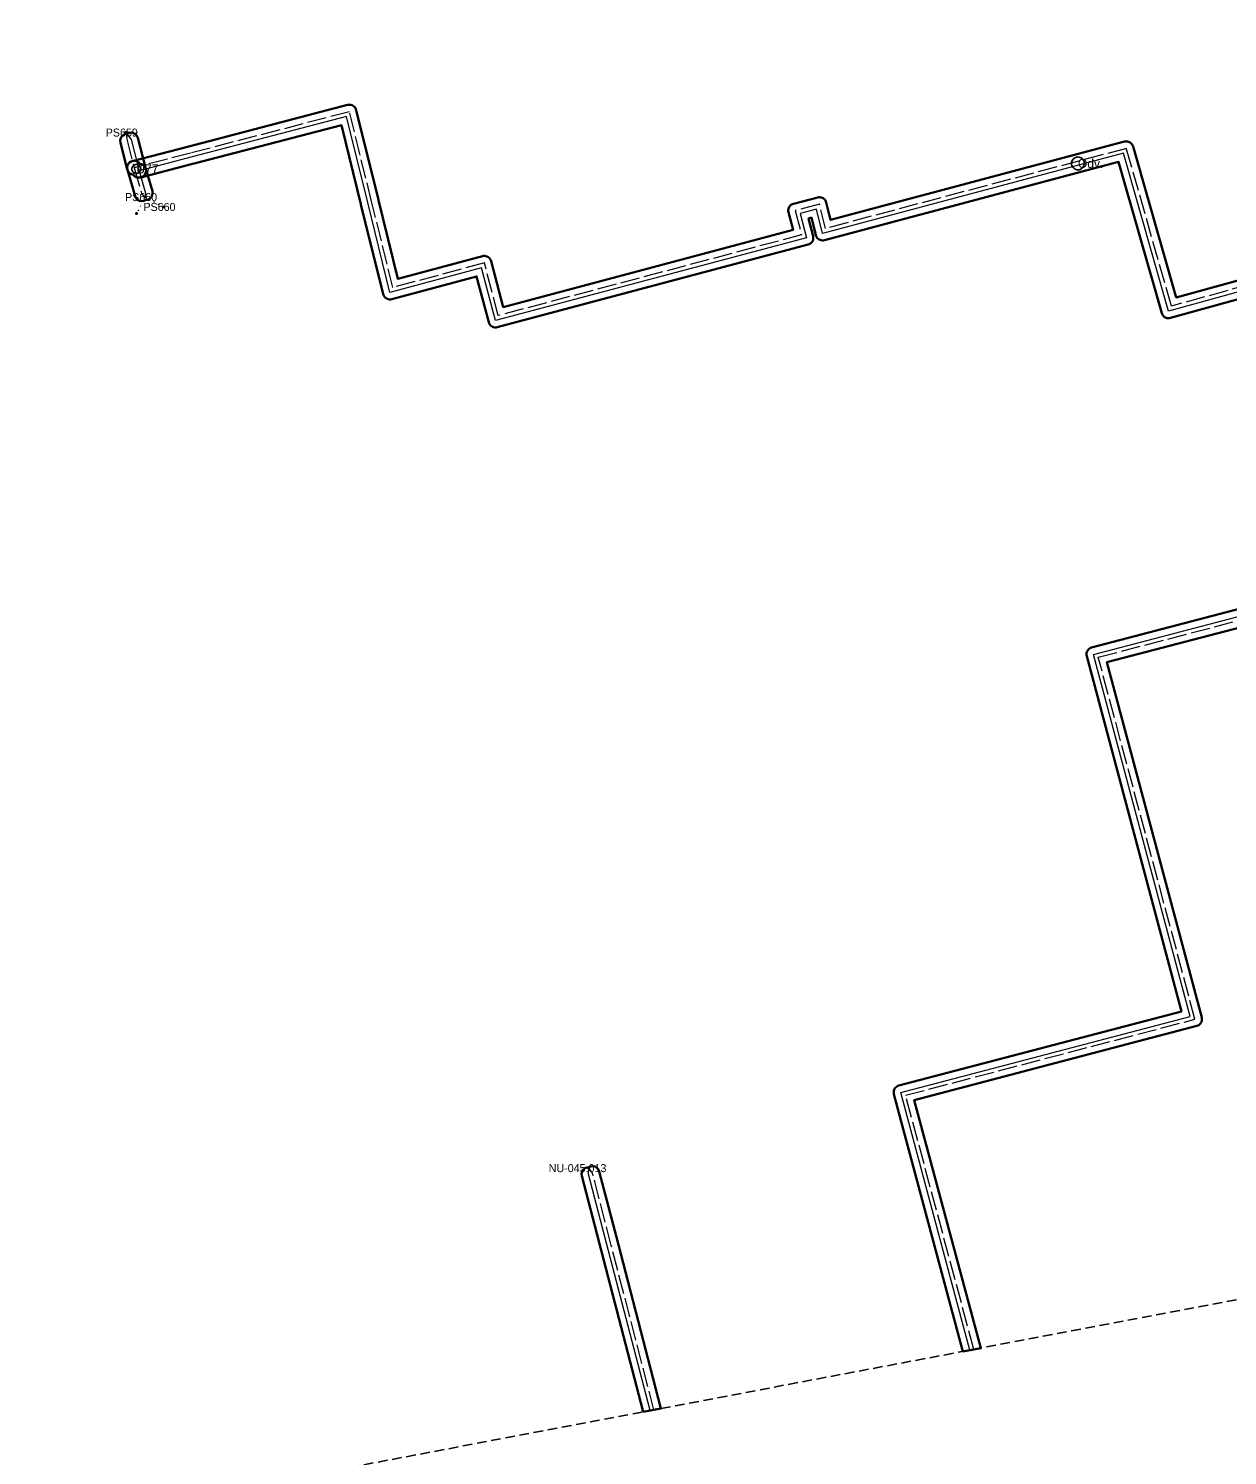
# Model space of a CAD drawing. Extents: x -452602 to -451136, y -1100088 to -1099653.
# Drawn here: x -451646 to -451526.1, y -1099905.8 to -1099763.2 of the extents above; entities that cross this region are included whole.
import ezdxf

# ---------------------------------------------------------------- set-up
doc = ezdxf.new("R2010")
doc.units = 0
doc.header["$LTSCALE"] = 0.32
doc.header["$PDMODE"] = 32
doc.header["$PDSIZE"] = 0.16
for name, pattern in [('DOTTED', [1.5, 0.3, -1.2]), ('LONG_DASHED', [7.5, 6, -1.5]), ('MEDIUM_DASHED', [4.5, 3, -1.5])]:
    doc.linetypes.add(name, pattern=pattern)
for name, color, linetype, lineweight in [('2', 7, 'Continuous', 13), ('3', 7, 'Continuous', 25), ('62', 7, 'MEDIUM_DASHED', 25), ('8', 7, 'Continuous', 35)]:
    doc.layers.add(name, color=color, linetype=linetype, lineweight=lineweight)
doc.layers.add('4', color=7, linetype='Continuous')
doc.layers.add('7', color=7, linetype='Continuous')

msp = doc.modelspace()

# ---------------------------------------------------------------- linework, layer by layer
at = {"layer": '2', "linetype": 'LONG_DASHED'}
for p, q in [((-451629.758, -1099775.646), (-451635.409, -1099777.116)), ((-451589.561, -1099877.625), (-451589.942, -1099877.122)), ((-451587.686, -1099884.846), (-451589.561, -1099877.625)), ((-451583.416, -1099901.289), (-451587.686, -1099884.846))]:
    msp.add_line(p, q, dxfattribs=at)
at = {"layer": '2'}
for p, q in [((-451629.595, -1099776.017), (-451634.909, -1099777.401)), ((-451589.95, -1099877.725), (-451589.942, -1099877.122)), ((-451583.81, -1099901.363), (-451589.95, -1099877.725))]:
    msp.add_line(p, q, dxfattribs=at)
at = {"layer": '2', "linetype": 'DOTTED'}
for q in [(-451635.162, -1099781.684), (-451632.472, -1099781.025)]:
    msp.add_line((-451634.313, -1099780.041), q, dxfattribs=at)
at = {"layer": '2', "linetype": 'LONG_DASHED'}
for points in [[(-451440.258, -1099765.721), (-451453.851, -1099769.417), (-451480.917, -1099777.002), (-451500.994, -1099782.511), (-451500.212, -1099785.292), (-451504.472, -1099786.44), (-451505.212, -1099783.669), (-451531.662, -1099790.934), (-451536.175, -1099775.177), (-451566.255, -1099783.181), (-451566.862, -1099780.756), (-451569.284, -1099781.379), (-451568.655, -1099783.82), (-451598.982, -1099791.89), (-451600.376, -1099786.618), (-451609.527, -1099789.083), (-451611.651, -1099780.495)], [(-451611.651, -1099780.495), (-451613.87, -1099771.51), (-451629.758, -1099775.646)], [(-451636.245, -1099773.591), (-451636.097, -1099774.397), (-451635.409, -1099777.116)], [(-451635.409, -1099777.116), (-451634.637, -1099779.752), (-451634.313, -1099780.041)], [(-451551.433, -1099895.241), (-451558.248, -1099869.833), (-451529.317, -1099862.234), (-451538.976, -1099826.048), (-451523.454, -1099821.982), (-451522.711, -1099824.236), (-451512.799, -1099821.592), (-451513.524, -1099818.868), (-451509.196, -1099817.785), (-451508.559, -1099820.425), (-451468.961, -1099809.725), (-451467.595, -1099809.356), (-451466.163, -1099814.028)]]:
    msp.add_lwpolyline(points, dxfattribs=at)
at = {"layer": '2'}
for points in [[(-451440.543, -1099766.212), (-451500.5, -1099782.791), (-451499.718, -1099785.574), (-451504.756, -1099786.93), (-451505.494, -1099784.161), (-451531.96, -1099791.453), (-451536.46, -1099775.666), (-451566.551, -1099783.675), (-451567.153, -1099781.244), (-451568.797, -1099781.667), (-451568.176, -1099784.107), (-451599.266, -1099792.381), (-451600.66, -1099787.109), (-451609.817, -1099789.576), (-451612.038, -1099780.59)], [(-451612.038, -1099780.59), (-451614.163, -1099772), (-451629.595, -1099776.017)], [(-451636.245, -1099773.591), (-451635.708, -1099774.296), (-451634.909, -1099777.401)], [(-451634.909, -1099777.401), (-451634.252, -1099779.64), (-451634.313, -1099780.041)], [(-451551.827, -1099895.315), (-451558.739, -1099869.548), (-451529.806, -1099861.951), (-451539.465, -1099825.761), (-451523.193, -1099821.5), (-451522.45, -1099823.752), (-451513.289, -1099821.307), (-451514.016, -1099818.579), (-451508.902, -1099817.3), (-451508.266, -1099819.931), (-451469.019, -1099809.326), (-451467.315, -1099808.865), (-451465.807, -1099813.902)]]:
    msp.add_lwpolyline(points, dxfattribs=at)
at = {"layer": '3'}
for points in [[(-451635.176, -1099776.777), (-451635.098, -1099776.784), (-451635.023, -1099776.804), (-451634.952, -1099776.837), (-451634.888, -1099776.881), (-451634.833, -1099776.937), (-451634.788, -1099777.001), (-451634.755, -1099777.071), (-451634.735, -1099777.147), (-451634.728, -1099777.225), (-451634.735, -1099777.302), (-451634.755, -1099777.378), (-451634.788, -1099777.448), (-451634.833, -1099777.512), (-451634.888, -1099777.567), (-451634.952, -1099777.612), (-451635.023, -1099777.645), (-451635.098, -1099777.665), (-451635.176, -1099777.672), (-451635.253, -1099777.665), (-451635.329, -1099777.645), (-451635.399, -1099777.612), (-451635.463, -1099777.567), (-451635.519, -1099777.512), (-451635.563, -1099777.448), (-451635.596, -1099777.378), (-451635.616, -1099777.302), (-451635.623, -1099777.225), (-451635.616, -1099777.147), (-451635.596, -1099777.071), (-451635.563, -1099777.001), (-451635.519, -1099776.937), (-451635.463, -1099776.881), (-451635.399, -1099776.837), (-451635.329, -1099776.804), (-451635.253, -1099776.784)], [(-451541.016, -1099776.031), (-451540.904, -1099776.041), (-451540.796, -1099776.07), (-451540.695, -1099776.117), (-451540.603, -1099776.181), (-451540.524, -1099776.26), (-451540.46, -1099776.352), (-451540.412, -1099776.454), (-451540.383, -1099776.562), (-451540.373, -1099776.673), (-451540.383, -1099776.785), (-451540.412, -1099776.893), (-451540.46, -1099776.994), (-451540.524, -1099777.086), (-451540.603, -1099777.165), (-451540.695, -1099777.229), (-451540.796, -1099777.277), (-451540.904, -1099777.306), (-451541.016, -1099777.315), (-451541.127, -1099777.306), (-451541.235, -1099777.277), (-451541.337, -1099777.229), (-451541.428, -1099777.165), (-451541.508, -1099777.086), (-451541.572, -1099776.994), (-451541.619, -1099776.893), (-451541.648, -1099776.785), (-451541.658, -1099776.673), (-451541.648, -1099776.562), (-451541.619, -1099776.454), (-451541.572, -1099776.352), (-451541.508, -1099776.26), (-451541.428, -1099776.181), (-451541.337, -1099776.117), (-451541.235, -1099776.07), (-451541.127, -1099776.041)]]:
    msp.add_lwpolyline(points, close=True, dxfattribs=at)
at = {"layer": '4'}
for p in [(-451636.245, -1099773.591), (-451634.313, -1099780.041), (-451632.472, -1099781.025), (-451635.162, -1099781.684), (-451589.942, -1099877.122)]:
    msp.add_point(p, dxfattribs=at)
at = {"layer": '62'}
msp.add_lwpolyline([(-451137.485, -1099816.961), (-452572.169, -1100088.267), (-452602.314, -1099919.678), (-451137.485, -1099652.838), (-451136.368, -1099701.963)], close=True, dxfattribs=at)
at = {"layer": '7'}
for p in [(-451636.245, -1099773.591), (-451634.313, -1099780.041), (-451589.942, -1099877.122)]:
    msp.add_point(p, dxfattribs=at)
at = {"layer": '8'}
for points in [[(-451635.962, -1099776.688), (-451635.884, -1099776.603), (-451635.794, -1099776.532), (-451635.693, -1099776.477), (-451635.585, -1099776.439), (-451629.935, -1099774.968), (-451614.047, -1099770.832), (-451613.938, -1099770.813), (-451613.827, -1099770.811), (-451613.718, -1099770.826), (-451613.612, -1099770.859), (-451613.512, -1099770.908), (-451613.422, -1099770.972), (-451613.343, -1099771.049), (-451613.277, -1099771.138), (-451613.226, -1099771.236), (-451613.191, -1099771.342), (-451610.971, -1099780.326), (-451610.969, -1099780.336), (-451609.019, -1099788.222), (-451600.559, -1099785.943), (-451600.45, -1099785.922), (-451600.34, -1099785.919), (-451600.231, -1099785.934), (-451600.125, -1099785.965), (-451600.026, -1099786.013), (-451599.935, -1099786.075), (-451599.855, -1099786.151), (-451599.789, -1099786.239), (-451599.736, -1099786.335), (-451599.7, -1099786.439), (-451598.484, -1099791.034), (-451569.506, -1099783.322), (-451569.962, -1099781.553), (-451569.98, -1099781.445), (-451569.982, -1099781.335), (-451569.967, -1099781.227), (-451569.935, -1099781.122), (-451569.886, -1099781.023), (-451569.823, -1099780.933), (-451569.747, -1099780.854), (-451569.659, -1099780.788), (-451569.562, -1099780.737), (-451569.458, -1099780.701), (-451567.037, -1099780.078), (-451566.928, -1099780.059), (-451566.818, -1099780.058), (-451566.709, -1099780.073), (-451566.604, -1099780.106), (-451566.505, -1099780.155), (-451566.414, -1099780.218), (-451566.336, -1099780.295), (-451566.27, -1099780.384), (-451566.219, -1099780.482), (-451566.184, -1099780.586), (-451565.748, -1099782.322), (-451536.355, -1099774.5), (-451536.237, -1099774.479), (-451536.116, -1099774.479), (-451535.997, -1099774.5), (-451535.884, -1099774.54), (-451535.779, -1099774.6), (-451535.686, -1099774.676), (-451535.607, -1099774.768), (-451535.546, -1099774.871), (-451535.503, -1099774.984), (-451531.179, -1099790.075), (-451505.397, -1099782.994)], [(-451505.988, -1099785.024), (-451531.774, -1099792.128), (-451531.894, -1099792.15), (-451532.015, -1099792.151), (-451532.135, -1099792.131), (-451532.249, -1099792.091), (-451532.355, -1099792.032), (-451532.449, -1099791.955), (-451532.528, -1099791.863), (-451532.59, -1099791.759), (-451532.633, -1099791.645), (-451536.944, -1099776.52), (-451566.371, -1099784.351), (-451566.48, -1099784.371), (-451566.591, -1099784.373), (-451566.701, -1099784.358), (-451566.808, -1099784.326), (-451566.907, -1099784.277), (-451566.998, -1099784.213), (-451567.078, -1099784.136), (-451567.144, -1099784.046), (-451567.196, -1099783.948), (-451567.231, -1099783.843), (-451567.663, -1099782.098), (-451567.946, -1099782.171), (-451567.497, -1099783.934), (-451567.478, -1099784.054), (-451567.479, -1099784.175), (-451567.501, -1099784.294), (-451567.543, -1099784.408), (-451567.605, -1099784.512), (-451567.683, -1099784.605), (-451567.777, -1099784.682), (-451567.882, -1099784.742), (-451567.996, -1099784.783), (-451599.086, -1099793.057), (-451599.206, -1099793.078), (-451599.327, -1099793.078), (-451599.447, -1099793.057), (-451599.562, -1099793.015), (-451599.667, -1099792.954), (-451599.76, -1099792.875), (-451599.839, -1099792.782), (-451599.9, -1099792.677), (-451599.942, -1099792.562), (-451601.157, -1099787.967), (-451609.634, -1099790.251), (-451609.744, -1099790.272), (-451609.855, -1099790.274), (-451609.965, -1099790.26), (-451610.072, -1099790.227), (-451610.172, -1099790.179), (-451610.263, -1099790.115), (-451610.343, -1099790.037), (-451610.409, -1099789.948), (-451610.461, -1099789.849), (-451610.496, -1099789.743), (-451612.714, -1099780.773), (-451612.718, -1099780.758), (-451612.722, -1099780.744), (-451614.672, -1099772.855), (-451629.412, -1099776.693), (-451629.419, -1099776.695), (-451629.426, -1099776.696), (-451634.732, -1099778.078), (-451634.779, -1099778.088), (-451634.853, -1099778.098), (-451634.972, -1099778.098), (-451635.089, -1099778.077), (-451635.2, -1099778.037), (-451635.304, -1099777.978), (-451635.396, -1099777.903), (-451635.474, -1099777.813), (-451635.587, -1099777.793), (-451635.695, -1099777.755), (-451635.796, -1099777.7), (-451635.886, -1099777.628), (-451635.964, -1099777.543), (-451636.026, -1099777.447), (-451636.071, -1099777.342), (-451636.099, -1099777.23), (-451636.109, -1099777.115), (-451636.099, -1099777.001), (-451636.071, -1099776.89), (-451636.025, -1099776.784)], [(-451523.913, -1099822.825), (-451538.118, -1099826.546), (-451528.64, -1099862.054), (-451528.62, -1099862.162), (-451528.618, -1099862.272), (-451528.632, -1099862.381), (-451528.664, -1099862.487), (-451528.711, -1099862.586), (-451528.774, -1099862.677), (-451528.85, -1099862.756), (-451528.938, -1099862.823), (-451529.035, -1099862.875), (-451529.139, -1099862.912), (-451557.39, -1099870.331), (-451550.743, -1099895.11), (-451552.517, -1099895.446), (-451559.415, -1099869.73), (-451559.435, -1099869.621), (-451559.438, -1099869.511), (-451559.423, -1099869.402), (-451559.391, -1099869.296), (-451559.344, -1099869.197), (-451559.281, -1099869.106), (-451559.205, -1099869.027), (-451559.117, -1099868.96), (-451559.02, -1099868.908), (-451558.916, -1099868.872), (-451530.664, -1099861.452), (-451540.142, -1099825.942), (-451540.162, -1099825.834), (-451540.164, -1099825.723), (-451540.15, -1099825.614), (-451540.118, -1099825.509), (-451540.071, -1099825.41), (-451540.008, -1099825.319), (-451539.932, -1099825.239), (-451539.844, -1099825.173), (-451539.747, -1099825.12), (-451539.643, -1099825.084), (-451523.37, -1099820.822)]]:
    msp.add_lwpolyline(points, dxfattribs=at)
for points in [[(-451635.467, -1099777.812), (-451635.668, -1099777.766), (-451635.857, -1099777.654), (-451636.001, -1099777.489), (-451636.087, -1099777.288), (-451636.775, -1099774.568), (-451636.795, -1099774.35), (-451636.746, -1099774.136), (-451636.634, -1099773.948), (-451636.469, -1099773.804), (-451636.268, -1099773.718), (-451636.071, -1099773.7), (-451635.883, -1099773.619), (-451635.665, -1099773.598), (-451635.451, -1099773.645), (-451635.263, -1099773.757), (-451635.118, -1099773.921), (-451635.031, -1099774.122), (-451634.231, -1099777.226), (-451634.21, -1099777.444), (-451634.257, -1099777.658), (-451634.369, -1099777.846), (-451634.533, -1099777.991), (-451634.734, -1099778.078), (-451634.952, -1099778.099), (-451635.166, -1099778.052), (-451635.354, -1099777.94)], [(-451634.842, -1099776.71), (-451634.673, -1099776.741), (-451634.481, -1099776.846), (-451634.33, -1099777.006), (-451634.237, -1099777.204), (-451633.581, -1099779.444), (-451633.553, -1099779.661), (-451633.593, -1099779.876), (-451633.699, -1099780.068), (-451633.858, -1099780.219), (-451634.056, -1099780.312), (-451634.258, -1099780.338), (-451634.44, -1099780.424), (-451634.657, -1099780.452), (-451634.872, -1099780.412), (-451635.064, -1099780.307), (-451635.215, -1099780.147), (-451635.308, -1099779.949), (-451636.08, -1099777.313), (-451636.108, -1099777.096), (-451636.068, -1099776.881), (-451635.962, -1099776.689), (-451635.803, -1099776.538), (-451635.605, -1099776.445), (-451635.388, -1099776.417), (-451635.173, -1099776.457), (-451634.981, -1099776.563)], [(-451584.499, -1099901.494), (-451590.627, -1099877.901), (-451590.648, -1099877.684), (-451590.601, -1099877.47), (-451590.49, -1099877.281), (-451590.326, -1099877.136), (-451590.126, -1099877.048), (-451589.921, -1099877.028), (-451589.737, -1099876.948), (-451589.52, -1099876.927), (-451589.306, -1099876.974), (-451589.117, -1099877.085), (-451588.972, -1099877.249), (-451588.884, -1099877.449), (-451587.044, -1099884.532), (-451587.037, -1099884.607), (-451587.009, -1099884.671), (-451582.727, -1099901.158)]]:
    msp.add_lwpolyline(points, close=True, dxfattribs=at)

# ---------------------------------------------------------------- texts
at = {"layer": '3'}
for s, p in [('U77 ', (-451635.176, -1099777.673)), ('Odv.', (-451541.016, -1099777.122))]:
    msp.add_text(s, height=0.9, dxfattribs=at).set_placement(p)
at = {"layer": '4'}
for s, p in [('PS659 ', (-451638.245, -1099773.991)), ('PS660 ', (-451636.313, -1099780.441)), ('PS660 ', (-451634.472, -1099781.425)), ('NU-045.013', (-451593.942, -1099877.522))]:
    msp.add_text(s, height=0.8, dxfattribs=at).set_placement(p)

doc.saveas('drawing.dxf')
